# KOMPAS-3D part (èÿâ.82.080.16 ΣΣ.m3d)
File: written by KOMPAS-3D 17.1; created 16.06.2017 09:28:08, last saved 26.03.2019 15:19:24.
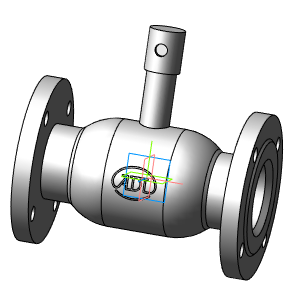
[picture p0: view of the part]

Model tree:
1. Операция без истории:2  (labels: Сталь 20  ГОСТ 1050-88)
